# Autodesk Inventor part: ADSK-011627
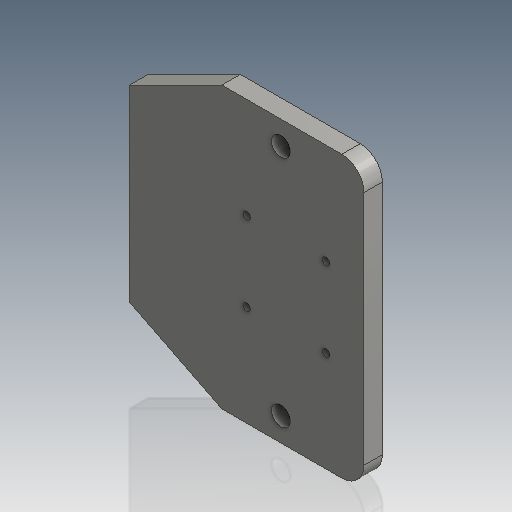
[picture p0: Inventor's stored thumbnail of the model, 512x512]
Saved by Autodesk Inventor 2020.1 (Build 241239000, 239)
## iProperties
Created: 2000-02
Part Number: ADSK-011627
Document SubType Name: Modeling
Description: PLT-06,FH,CP,03,060,050,STOP
Designer: cmcgourin
Material: Pearson HRS
Density: 7.83 g/cm^3
Appearance: Steel
Mass: 1391.49 g
Surface Area: 418.054 cm^2
Volume: 177.713 cm^3
Control State: 0
Checked Out: False
Master: False
Shininess: 25.0
Length Units: 11269
Angle Units: 11279
Time Units: 11290
Mass Units: 11283
Length Display Precision: 3
Angle Display Precision: 2
Compacted: True
Cutlength: 6
Material Desc: FLAT,HRS,0.375X05.000
Material_Number: A084412
Dimensions: 127x152x10 mm
Mass: 1,391 kg
DocNumber: ADSK-011627.ipt
Folder: 01 - Themengebiete\Simplification\01 - Packaging machine\
VDS_Category: 3D Komponenten
Density: 7.83
Volumn: 130.12171886180727
Area: 324.97695245549414
PropertySet Name: Model Information
Author: cmcgourin
Revision Number: -
Title: base plate
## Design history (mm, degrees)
node "Extrusion1" dims "d3" = 10, "d4" = 0
  sketch "Sketch1"
    geometry: L1 (-63.5, -76)-(63.5, -76); L2 (63.5, -76)-(63.5, 76); L3 (63.5, 76)-(-63.5, 76); L4 (-63.5, 76)-(-63.5, -76); 3 further points
    constraints: 8 end point, 2 midpoint, 2 parallel, 1 horizontal, 1 horizontal alignment, 1 perpendicular, 1 vertical alignment
    dimensions: "d21" = 127 distance of L2.end L3.end; "d22" = 152 distance of L3.end L1.start
node "Chamfer1" dims "d23" = 25.4, "d24" = 25.4, "d45" = 45 deg
node "Chamfer2" dims "d25" = 50, "d26" = 25, "d46" = 45 deg
node "Chamfer3" dims "d27" = 25, "d28" = 50, "d47" = 45 deg
node "Fillet1" dims "d29" = 12
node "Hole3" dims "d33" = 10.31875, "d34" = 9.525, "d35" = 6.35, "d36" = 60 deg, "d37" = 19.05, "d38" = 118 deg
  sketch "Sketch4"
    geometry: L1 (-63.5, -64)-(-63.5, 64) reference; L2 (-18.5, 63.25)-(-18.5, -63.25); 2 further points
    constraints: 2 end point, 2 midpoint, 1 horizontal alignment, 1 vertical, 1 vertical alignment
    dimensions: "d30" = 45 distance from line of L1 L2.start; "d48" = 126.5 distance of L2.start L2.end
node "Hole4" dims "d39" = 4.134, "d40" = 9.525, "d41" = 6.35, "d42" = 60 deg, "d43" = 19.05, "d44" = 118 deg, "d52" = 10
  sketch "Sketch5"
    geometry: L1 (0, -21.5)-(-43, -21.5); L2 (-43, -21.5)-(-43, 21.5); L3 (-43, 21.5)-(0, 21.5); L4 (0, 21.5)-(0, -21.5); L5 (-63.5, -64)-(-63.5, 64) reference; 6 further points
    constraints: 8 end point, 4 coincident, 2 midpoint, 2 parallel, 1 horizontal, 1 horizontal alignment, 1 perpendicular
    dimensions: "d49" = 20.5 distance between parallel lines of L5 L2; "d50" = 43 distance of L3.end L1.start; "d51" = 43 distance of L2.end L3.end (= d50)
node "Solide1"
node "Corps solides"
node "Corps surfaciques"
